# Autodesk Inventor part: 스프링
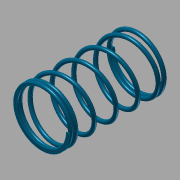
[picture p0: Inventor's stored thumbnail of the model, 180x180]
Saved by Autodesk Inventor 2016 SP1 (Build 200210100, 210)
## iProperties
Created: 2019-02
Part Number: 스프링
Material: 강철
Document SubType Name: Modeling
Designer: mduedu
Density: 2.18 g/cm^3
Appearance: 하늘색 짙음
CustomPartVersion: 1
Author: mduedu
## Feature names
1. Main Coil Feature(R)
2. Coil  Start Transition 2(R)
3. Coil  Start Transition 3(R)
4. Coil  Start Transition 4(R)
5. Plain Ends Cut  2(R) [Extrusion]
6. Main Coil Feature(L)
7. Cut Plain Ends Cut 1(L) [Extrusion]
8. Cut Plain Ends Cut 2(L) [Extrusion]
## Parameters: d0 = 0.25 mm, da_d = 1 mm, da_D2 = 13 mm, da_ti = 5.79943 mm, da_nz1 = 15 mm, spiral_Angle = 1.31102 mm, d2 = 5.79943 mm, d4 = 32.5 mm, d5 = 0, d6 = 90 deg, d7 = 90 deg, d8 = 0, d9 = 0, d12 = 3.09988 mm, d13 = -4.05199 mm, d14 = 1 mm, d15 = 0, d16 = 4.59957 mm, d18 = 2.5 mm, d19 = 0, d20 = 90 deg, d21 = 90 deg, d22 = 0, d23 = 0, d24 = 3.39971 mm, d26 = 2.5 mm, d27 = 0, d28 = 90 deg, d29 = 90 deg, d30 = 0, d31 = 0, d32 = 2.19986 mm, d34 = 2.5 mm, d35 = 0, d36 = 90 deg, d37 = 90 deg, d38 = 0, d39 = 0, d40 = 1 mm, d42 = 2.5 mm, d43 = 0, d44 = 90 deg, d45 = 90 deg, d46 = 0, d47 = 0, d48 = 4.59957 mm, d50 = 1.875 mm, d51 = 0, d52 = 90 deg, d53 = 90 deg, d54 = 0, d55 = 0, d56 = 3.39971 mm, d58 = 1.875 mm, d59 = 0, d60 = 90 deg, d61 = 90 deg, d62 = 0, d63 = 0, d64 = 2.19986 mm, d66 = 1.875 mm, d67 = 0, d68 = 90 deg, d69 = 90 deg, d70 = 0, d71 = 0, d72 = 1 mm, d74 = 1.875 mm, d75 = 0, d76 = 90 deg, d77 = 90 deg, d78 = 0, d79 = 0, End_Pitch = 1.00866 mm, d82 = 15 mm, d83 = 0, d84 = 90 deg, d85 = 90 deg, d86 = 0, d87 = 0, d88 = 1.00866 mm, d91 = 0, d92 = 90 deg, d93 = 90 deg, d94 = 0, d95 = 0, d96 = 15 mm, d97 = 1.00866 mm, d98 = 0, d99 = 15 mm, d100 = 1.00866 mm, d101 = 0, d102 = 0, d103 = 0, d104 = 0, d105 = 0, d106 = 0, d108 = 0, d112 = 0, d113 = 0, d114 = 0, const_zero = 0, Not_rightdir = 0, d121 = 0.26078 mm, d131 = 0, d132 = 0, d133 = 0, d134 = 0, d135 = 0.25 mm, d137 = 5.79943 mm, d139 = 32.5 mm, d140 = 0, d141 = 90 deg, d142 = 90 deg, d143 = 0, d144 = 0, d145 = 3.09988 mm, d146 = -4.05199 mm, d147 = 0.26078 mm, d148 = 0.00862 mm, d149 = 1 mm, d150 = 0, d151 = 0, d152 = 4.59957 mm, d154 = 2.5 mm, d155 = 0, d156 = 90 deg, d157 = 90 deg, d158 = 0, d159 = 0, d160 = 3.39971 mm, d162 = 2.5 mm, d163 = 0, d164 = 90 deg, d165 = 90 deg, d166 = 0, d167 = 0, d168 = 2.19986 mm, d170 = 2.5 mm, d171 = 0, d172 = 90 deg, d173 = 90 deg, d174 = 0, d175 = 0, d176 = 1 mm, d178 = 2.5 mm, d179 = 0, d180 = 90 deg, d181 = 90 deg, d182 = 0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
